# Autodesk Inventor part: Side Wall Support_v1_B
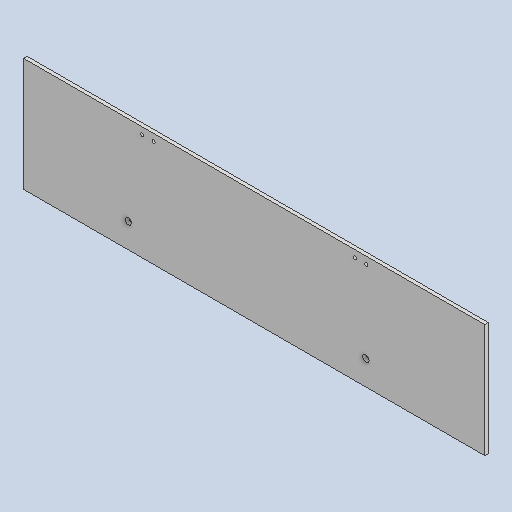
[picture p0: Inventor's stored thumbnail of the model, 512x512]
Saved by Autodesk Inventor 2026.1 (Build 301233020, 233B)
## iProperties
Created: 2026-10
Part Number: Side Wall Support_v1_B
Material: Generic
Document SubType Name: Modeling
Designer: hp
Density: 1 g/cm^3
Appearance: Default
Author: hp
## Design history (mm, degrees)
sketch "Sketch1"
  geometry: L1 (0, 0)-(700, 0); L2 (700, 160)-(0, 160); L3 (0, 160)-(0, 0); L4 (700, 160)-(700, 0); L5 (50, 160)-(50, 0)
  constraints: 10 end point, 2 point on line, 1 horizontal, 1 parallel, 1 perpendicular, 1 vertical
  dimensions: "d28" = 700 distance of L2.start L2.end; "d29" = 160 distance of L2.end L1.start; "d48" = 50 distance between parallel lines of L3 L5
extrude "Extrusion2" new body sketch "Sketch1" distance "d23" = 5; taper "d24" = 0 deg
sketch "Sketch4"
  geometry: 4 further points
hole "Hole1" sketch "Sketch4" at (217, 150), (233, 150), (517, 150), (533, 150) diameter "d49" = 4.5; stored, may be unused: countersink angle "d53" = 90 deg, drill point angle "d55" = 0 deg; dims "d50" = 6, "d51" = 4, "d52" = 2, "d54" = 8
sketch "Sketch5"
  geometry: 2 further points
hole "Hole2" sketch "Sketch5" at (197.5, 35), (532.5, 35) diameter "d56" = 9; stored, may be unused: countersink angle "d60" = 90 deg, drill point angle "d62" = 0 deg; dims "d57" = 6, "d58" = 4, "d59" = 2, "d61" = 8
body "Solid2"
